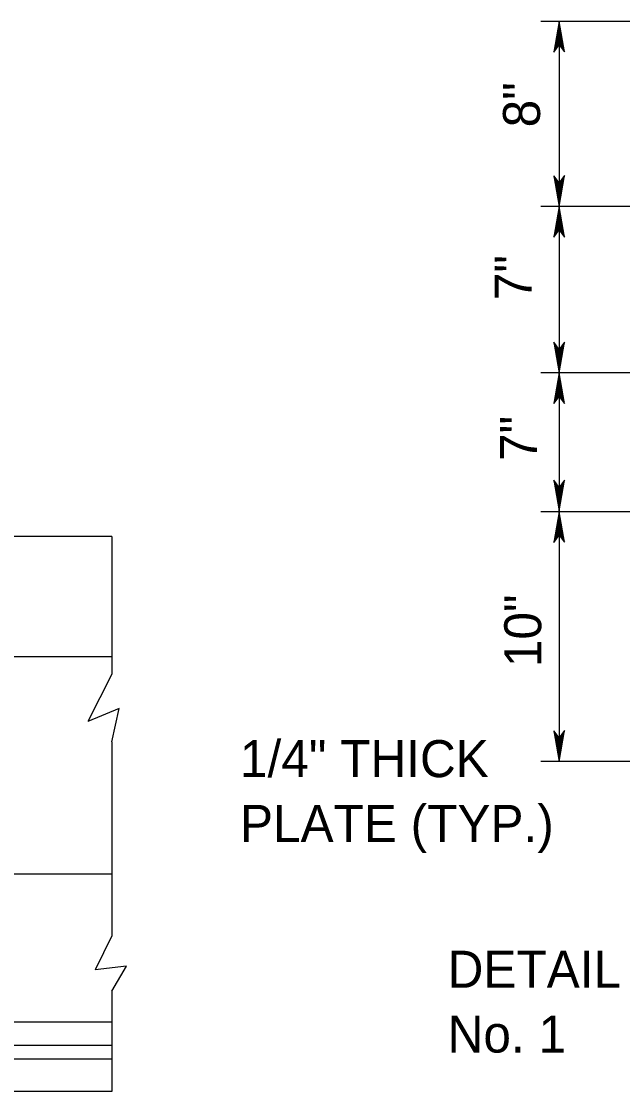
# Model space of a CAD drawing. Extents: x 499883 to 500983, y 499104 to 499764.
# Drawn here: x 500228.2 to 500293.1, y 499581.2 to 499696.8 of the extents above; entities that cross this region are included whole.
import ezdxf

# ---------------------------------------------------------------- set-up
doc = ezdxf.new("R2010")
doc.units = 0
doc.layers.add('5', color=7, linetype='Continuous')

msp = doc.modelspace()

# ---------------------------------------------------------------- linework, layer by layer
at = {"layer": '5'}
for p, q in [((500295.68, 499696.81), (500284.28, 499696.81)), ((500286.28, 499696.81), (500286.28, 499676.83)), ((500296.99, 499676.83), (500284.28, 499676.83)), ((500286.28, 499676.83), (500286.28, 499658.84)), ((500296.99, 499658.84), (500284.28, 499658.84)), ((500286.28, 499658.84), (500286.28, 499643.85)), ((500295.93, 499643.85), (500284.28, 499643.85)), ((500286.28, 499643.85), (500286.28, 499616.88)), ((500237.96, 499641.16), (500164.74, 499641.16)), ((500237.96, 499641.16), (500237.96, 499626.28)), ((500237.96, 499628.17), (500166.73, 499628.17)), ((500237.96, 499626.28), (500235.37, 499621.19)), ((500238.77, 499622.59), (500235.37, 499621.19)), ((500237.96, 499619), (500238.77, 499622.59)), ((500237.96, 499619), (500237.96, 499598.03)), ((500295.68, 499616.88), (500284.28, 499616.88)), ((500237.96, 499604.68), (500156.74, 499604.68)), ((500237.96, 499598.03), (500236.17, 499594.34)), ((500239.56, 499594.74), (500236.17, 499594.34)), ((500237.96, 499592.05), (500239.56, 499594.74)), ((500237.96, 499592.05), (500237.96, 499581.2)), ((500237.96, 499588.7), (500166.73, 499588.7)), ((500237.96, 499586.2), (500156.74, 499586.2)), ((500237.96, 499584.7), (500156.74, 499584.7)), ((500237.96, 499581.2), (500156.74, 499581.2))]:
    msp.add_line(p, q, dxfattribs=at)
for points in [[(500286.28, 499696.81), (500285.69, 499693.49), (500286.28, 499694.28), (500286.85, 499693.51), (500286.28, 499696.81), (500286.28, 499696.59), (500285.73, 499693.58), (500286.28, 499694.35), (500286.81, 499693.64), (500286.29, 499696.47), (500286.28, 499696.36), (500285.82, 499693.79), (500286.28, 499694.36), (500286.73, 499693.77), (500286.27, 499696.31), (500286.29, 499696.2), (500285.88, 499693.95), (500286.27, 499694.39), (500286.68, 499693.94), (500286.29, 499695.88), (500286.29, 499695.69), (500285.97, 499694.12), (500286.27, 499694.42), (500286.6, 499694.09), (500286.28, 499695.66), (500286.26, 499695.48), (500286.06, 499694.3), (500286.29, 499694.53), (500286.52, 499694.28), (500286.28, 499695.32), (500286.26, 499695.15), (500286.12, 499694.44), (500286.28, 499694.56), (500286.46, 499694.36), (500286.27, 499695.07), (500286.16, 499694.6), (500286.29, 499694.67), (500286.42, 499694.46), (500286.29, 499694.95), (500286.22, 499694.64), (500286.32, 499694.77), (500286.38, 499694.63), (500286.28, 499694.77), (500286.27, 499694.69)], [(500286.28, 499676.83), (500286.86, 499680.15), (500286.28, 499679.36), (500285.7, 499680.14), (500286.28, 499676.83), (500286.27, 499677.05), (500286.82, 499680.06), (500286.27, 499679.3), (500285.74, 499680), (500286.26, 499677.17), (500286.28, 499677.28), (500286.73, 499679.86), (500286.27, 499679.28), (500285.82, 499679.87), (500286.28, 499677.33), (500286.26, 499677.44), (500286.67, 499679.7), (500286.28, 499679.26), (500285.87, 499679.7), (500286.26, 499677.76), (500286.26, 499677.95), (500286.58, 499679.53), (500286.28, 499679.22), (500285.95, 499679.55), (500286.28, 499677.98), (500286.29, 499678.16), (500286.49, 499679.35), (500286.26, 499679.12), (500286.03, 499679.37), (500286.28, 499678.32), (500286.29, 499678.49), (500286.43, 499679.2), (500286.27, 499679.09), (500286.09, 499679.28), (500286.28, 499678.58), (500286.39, 499679.04), (500286.26, 499678.98), (500286.13, 499679.18), (500286.26, 499678.7), (500286.33, 499679), (500286.23, 499678.87), (500286.17, 499679.02), (500286.27, 499678.87), (500286.28, 499678.95)], [(500286.28, 499676.83), (500285.69, 499673.51), (500286.28, 499674.3), (500286.85, 499673.52), (500286.28, 499676.83), (500286.28, 499676.61), (500285.73, 499673.6), (500286.28, 499674.36), (500286.81, 499673.66), (500286.29, 499676.49), (500286.28, 499676.38), (500285.82, 499673.8), (500286.28, 499674.38), (500286.73, 499673.78), (500286.27, 499676.33), (500286.29, 499676.22), (500285.88, 499673.96), (500286.27, 499674.4), (500286.68, 499673.95), (500286.29, 499675.9), (500286.29, 499675.71), (500285.97, 499674.13), (500286.27, 499674.44), (500286.6, 499674.11), (500286.28, 499675.68), (500286.26, 499675.5), (500286.06, 499674.31), (500286.29, 499674.54), (500286.52, 499674.29), (500286.28, 499675.34), (500286.26, 499675.17), (500286.12, 499674.46), (500286.28, 499674.57), (500286.46, 499674.38), (500286.27, 499675.08), (500286.16, 499674.62), (500286.29, 499674.68), (500286.42, 499674.48), (500286.29, 499674.96), (500286.22, 499674.66), (500286.32, 499674.79), (500286.38, 499674.64), (500286.28, 499674.79), (500286.27, 499674.71)], [(500286.28, 499658.84), (500286.86, 499662.17), (500286.28, 499661.37), (500285.7, 499662.15), (500286.28, 499658.84), (500286.27, 499659.06), (500286.82, 499662.07), (500286.27, 499661.31), (500285.74, 499662.02), (500286.26, 499659.18), (500286.28, 499659.29), (500286.73, 499661.87), (500286.27, 499661.29), (500285.82, 499661.89), (500286.28, 499659.34), (500286.26, 499659.45), (500286.67, 499661.71), (500286.28, 499661.27), (500285.87, 499661.72), (500286.26, 499659.78), (500286.26, 499659.96), (500286.58, 499661.54), (500286.28, 499661.23), (500285.95, 499661.57), (500286.28, 499660), (500286.29, 499660.17), (500286.49, 499661.36), (500286.26, 499661.13), (500286.03, 499661.38), (500286.28, 499660.34), (500286.29, 499660.5), (500286.43, 499661.22), (500286.27, 499661.1), (500286.09, 499661.29), (500286.28, 499660.59), (500286.39, 499661.06), (500286.26, 499660.99), (500286.13, 499661.19), (500286.26, 499660.71), (500286.33, 499661.01), (500286.23, 499660.89), (500286.17, 499661.03), (500286.27, 499660.89), (500286.28, 499660.96)], [(500286.28, 499658.84), (500285.69, 499655.52), (500286.28, 499656.31), (500286.85, 499655.54), (500286.28, 499658.84), (500286.28, 499658.62), (500285.73, 499655.61), (500286.28, 499656.38), (500286.81, 499655.67), (500286.29, 499658.5), (500286.28, 499658.39), (500285.82, 499655.81), (500286.28, 499656.39), (500286.73, 499655.8), (500286.27, 499658.34), (500286.29, 499658.23), (500285.88, 499655.98), (500286.27, 499656.42), (500286.68, 499655.97), (500286.29, 499657.91), (500286.29, 499657.72), (500285.97, 499656.15), (500286.27, 499656.45), (500286.6, 499656.12), (500286.28, 499657.69), (500286.26, 499657.51), (500286.06, 499656.33), (500286.29, 499656.55), (500286.52, 499656.31), (500286.28, 499657.35), (500286.26, 499657.18), (500286.12, 499656.47), (500286.28, 499656.59), (500286.46, 499656.39), (500286.27, 499657.09), (500286.16, 499656.63), (500286.29, 499656.7), (500286.42, 499656.49), (500286.29, 499656.98), (500286.22, 499656.67), (500286.32, 499656.8), (500286.38, 499656.65), (500286.28, 499656.8), (500286.27, 499656.72)], [(500286.28, 499643.94), (500286.86, 499647.26), (500286.28, 499646.47), (500285.7, 499647.24), (500286.28, 499643.94), (500286.27, 499644.16), (500286.82, 499647.17), (500286.27, 499646.41), (500285.74, 499647.11), (500286.26, 499644.28), (500286.28, 499644.39), (500286.73, 499646.97), (500286.27, 499646.39), (500285.82, 499646.98), (500286.28, 499644.44), (500286.26, 499644.55), (500286.67, 499646.8), (500286.28, 499646.37), (500285.87, 499646.81), (500286.26, 499644.87), (500286.26, 499645.06), (500286.58, 499646.64), (500286.28, 499646.33), (500285.95, 499646.66), (500286.28, 499645.09), (500286.29, 499645.27), (500286.49, 499646.46), (500286.26, 499646.23), (500286.03, 499646.48), (500286.28, 499645.43), (500286.29, 499645.6), (500286.43, 499646.31), (500286.27, 499646.2), (500286.09, 499646.39), (500286.28, 499645.69), (500286.39, 499646.15), (500286.26, 499646.08), (500286.13, 499646.29), (500286.26, 499645.8), (500286.33, 499646.11), (500286.23, 499645.98), (500286.17, 499646.13), (500286.27, 499645.98), (500286.28, 499646.06)], [(500286.28, 499643.85), (500285.69, 499640.53), (500286.28, 499641.32), (500286.85, 499640.55), (500286.28, 499643.85), (500286.28, 499643.63), (500285.73, 499640.62), (500286.28, 499641.39), (500286.81, 499640.68), (500286.29, 499643.51), (500286.28, 499643.4), (500285.82, 499640.83), (500286.28, 499641.4), (500286.73, 499640.81), (500286.27, 499643.35), (500286.29, 499643.24), (500285.88, 499640.99), (500286.27, 499641.43), (500286.68, 499640.98), (500286.29, 499642.92), (500286.29, 499642.73), (500285.97, 499641.16), (500286.27, 499641.46), (500286.6, 499641.13), (500286.28, 499642.7), (500286.26, 499642.52), (500286.06, 499641.34), (500286.29, 499641.57), (500286.52, 499641.32), (500286.28, 499642.36), (500286.26, 499642.19), (500286.12, 499641.48), (500286.28, 499641.6), (500286.46, 499641.4), (500286.27, 499642.11), (500286.16, 499641.64), (500286.29, 499641.71), (500286.42, 499641.5), (500286.29, 499641.99), (500286.22, 499641.68), (500286.32, 499641.81), (500286.38, 499641.67), (500286.28, 499641.81), (500286.27, 499641.73)], [(500286.28, 499616.88), (500286.86, 499620.2), (500286.28, 499619.41), (500285.7, 499620.18), (500286.28, 499616.88), (500286.27, 499617.1), (500286.82, 499620.11), (500286.27, 499619.34), (500285.74, 499620.05), (500286.26, 499617.22), (500286.28, 499617.33), (500286.73, 499619.9), (500286.27, 499619.33), (500285.82, 499619.92), (500286.28, 499617.38), (500286.26, 499617.49), (500286.67, 499619.74), (500286.28, 499619.3), (500285.87, 499619.75), (500286.26, 499617.81), (500286.26, 499618), (500286.58, 499619.57), (500286.28, 499619.27), (500285.95, 499619.6), (500286.28, 499618.03), (500286.29, 499618.21), (500286.49, 499619.39), (500286.26, 499619.16), (500286.03, 499619.41), (500286.28, 499618.37), (500286.29, 499618.54), (500286.43, 499619.25), (500286.27, 499619.13), (500286.09, 499619.33), (500286.28, 499618.62), (500286.39, 499619.09), (500286.26, 499619.02), (500286.13, 499619.23), (500286.26, 499618.74), (500286.33, 499619.05), (500286.23, 499618.92), (500286.17, 499619.06), (500286.27, 499618.92), (500286.28, 499618.99)]]:
    msp.add_lwpolyline(points, dxfattribs=at)

# ---------------------------------------------------------------- texts
for s, p in [('8"', (500284.21, 499685.37)), ('7"', (500283.3, 499666.7)), ('7"', (500283.88, 499649.33)), ('10"', (500284.34, 499627.06))]:
    msp.add_text(s, height=4, rotation=90, dxfattribs=at).set_placement(p)
for s, p in [('1/4" THICK', (500251.81, 499615.17)), ('PLATE (TYP.)', (500251.81, 499608.17)), ('DETAIL', (500274.23, 499592.42)), ('No. 1', (500274.23, 499585.42))]:
    msp.add_text(s, height=4, dxfattribs=at).set_placement(p)

doc.saveas('drawing.dxf')
